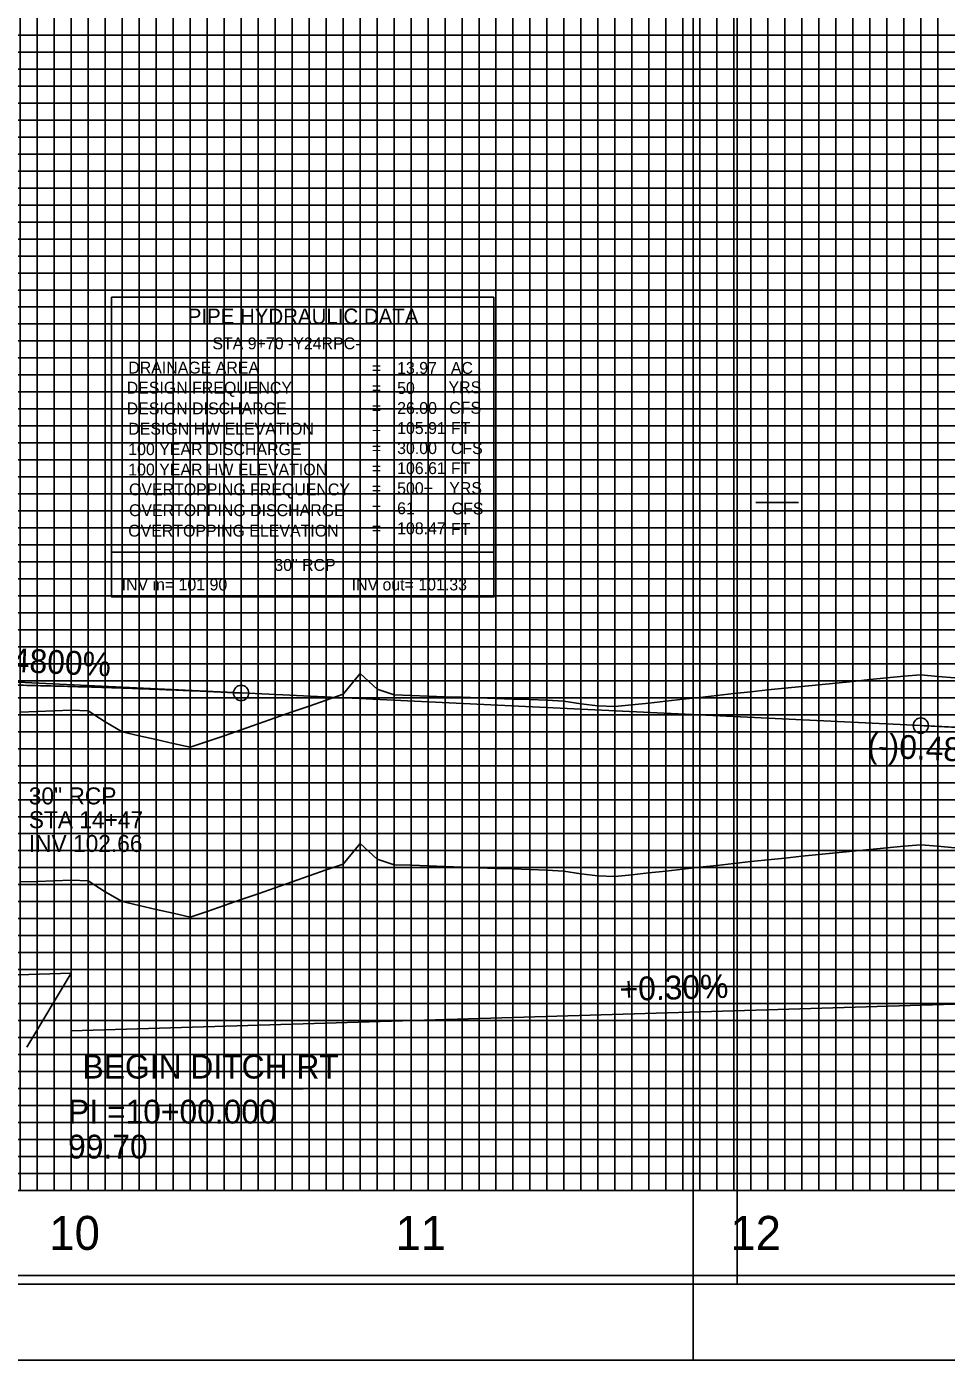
# Model space of a CAD drawing. Extents: x 2345490 to 2436403, y 465165 to 573888.
# Drawn here: x 2411882.2 to 2412152.8, y 527722 to 528114.5 of the extents above; entities that cross this region are included whole.
import ezdxf

# ---------------------------------------------------------------- set-up
doc = ezdxf.new("R2010")
doc.units = 0
for name, color, linetype in [('Old_Level_1', 7, 'Continuous'), ('Old_Level_18', 7, 'Continuous'), ('Old_Level_2', 7, 'Continuous'), ('Old_Level_3', 7, 'Continuous'), ('Old_Level_4', 7, 'Continuous'), ('Old_Level_41', 7, 'Continuous'), ('Old_Level_42', 7, 'Continuous'), ('Old_Level_43', 7, 'Continuous'), ('Old_Level_50', 7, 'Continuous'), ('Old_Level_51', 7, 'Continuous'), ('Old_Level_52', 7, 'Continuous'), ('Old_Level_62', 7, 'Continuous'), ('Old_Level_63', 7, 'Continuous')]:
    doc.layers.add(name, color=color, linetype=linetype)

msp = doc.modelspace()

# ---------------------------------------------------------------- linework, layer by layer
at = {"layer": 'Old_Level_1'}
for points in [[(2411895.325, 527863.353), (2411900.325, 527863.1465), (2411905.325, 527859.92), (2411910.325, 527857.03625), (2411915.325, 527855.8775), (2411920.325, 527854.73775), (2411925.325, 527853.61675), (2411930.325, 527852.51475), (2411935.325, 527854.12925), (2411940.325, 527855.877), (2411945.325, 527857.6245), (2411950.325, 527859.371), (2411955.325, 527861.11725), (2411960.325, 527862.8625), (2411965.325, 527864.60725), (2411970.325, 527866.35125), (2411975.325, 527868.0945), (2411980.325, 527874.1555), (2411985.325, 527869.5275), (2411990.325, 527867.9145), (2411995.325, 527867.72675), (2412000.325, 527867.54175), (2412005.325, 527867.36025), (2412010.325, 527867.18175), (2412015.325, 527867.0065), (2412020.325, 527866.8345), (2412025.325, 527866.66575), (2412030.325, 527866.5), (2412035.325, 527866.3375), (2412040.325, 527865.99575), (2412045.325, 527865.25), (2412050.325, 527864.65625), (2412055.325, 527864.43675), (2412060.325, 527864.91075), (2412065.325, 527865.47175), (2412070.325, 527866.032), (2412075.325, 527866.5915), (2412080.325, 527867.15025), (2412085.325, 527867.70825), (2412090.325, 527868.2655), (2412095.325, 527868.82225), (2412100.325, 527869.36725), (2412105.325, 527869.87), (2412110.325, 527870.372), (2412115.325, 527870.87325), (2412120.325, 527871.3735), (2412125.325, 527871.873), (2412130.325, 527872.37175), (2412135.325, 527872.8695), (2412140.325, 527873.36675), (2412145.325, 527873.74225), (2412150.325, 527873.32075), (2412155.325, 527872.89975)], [(2411880.325, 527862.82425), (2411885.325, 527862.99775), (2411890.325, 527863.174), (2411895.325, 527863.353)]]:
    msp.add_lwpolyline(points, dxfattribs=at)
at = {"layer": 'Old_Level_18'}
msp.add_lwpolyline([(2412345.325, 528797.04275), (2410845.325, 528797.04275), (2410845.325, 527747.04275), (2412345.325, 527747.04275)], close=True, dxfattribs=at)
at = {"layer": 'Old_Level_2'}
for p, q in [((2411945.325, 527918.443), (2411848.072, 527923.11125)), ((2411945.325, 527918.443), (2412145.325, 527908.843)), ((2412145.325, 527908.843), (2412242.57825, 527904.175))]:
    msp.add_line(p, q, dxfattribs=at)
for centre in [(2411945.325, 527918.443), (2412145.325, 527908.843)]:
    msp.add_circle(centre, 2.25, dxfattribs=at)
for points in [[(2411745.325, 527920.243), (2411749.325, 527920.36), (2411753.325, 527920.47075), (2411757.325, 527920.575), (2411761.325, 527920.67325), (2411765.325, 527920.765), (2411769.325, 527920.85075), (2411773.325, 527920.93025), (2411777.325, 527921.0035), (2411781.325, 527921.0705), (2411785.325, 527921.131), (2411789.325, 527921.1855), (2411793.325, 527921.23375), (2411797.325, 527921.27575), (2411801.325, 527921.3115), (2411805.325, 527921.341), (2411809.325, 527921.3645), (2411813.325, 527921.3815), (2411817.325, 527921.39225), (2411821.325, 527921.39675), (2411825.325, 527921.395), (2411829.325, 527921.38725), (2411833.325, 527921.373), (2411837.325, 527921.35275), (2411841.325, 527921.326), (2411845.325, 527921.293), (2411849.325, 527921.254), (2411853.325, 527921.20875), (2411857.325, 527921.157), (2411861.325, 527921.09925), (2411865.325, 527921.035), (2411869.325, 527920.96475), (2411873.325, 527920.88825), (2411877.325, 527920.8055), (2411881.325, 527920.7165), (2411885.325, 527920.621), (2411889.325, 527920.5195), (2411893.325, 527920.41175), (2411897.325, 527920.29775), (2411901.325, 527920.1775), (2411905.325, 527920.051), (2411909.325, 527919.9185), (2411913.325, 527919.7795), (2411917.325, 527919.63425), (2411921.325, 527919.48275), (2411925.325, 527919.325), (2411929.325, 527919.16125), (2411933.325, 527918.991), (2411937.325, 527918.81475), (2411941.325, 527918.632), (2411945.325, 527918.443)], [(2412145.325, 527908.843), (2412149.325, 527908.6555), (2412153.325, 527908.47675), (2412157.325, 527908.3065), (2412161.325, 527908.14525), (2412165.325, 527907.99275), (2412169.325, 527907.849), (2412173.325, 527907.714), (2412177.325, 527907.58775), (2412181.325, 527907.4705), (2412185.325, 527907.36175), (2412189.325, 527907.262), (2412193.325, 527907.17075), (2412197.325, 527907.0885), (2412201.325, 527907.015), (2412205.325, 527906.95), (2412209.325, 527906.894), (2412213.325, 527906.84675), (2412217.325, 527906.8085), (2412221.325, 527906.77875), (2412225.325, 527906.75775), (2412229.325, 527906.74575), (2412233.325, 527906.74225), (2412237.325, 527906.74775), (2412241.325, 527906.76175), (2412245.325, 527906.78475), (2412249.325, 527906.8165), (2412253.325, 527906.857), (2412257.325, 527906.90625), (2412261.325, 527906.96425), (2412265.325, 527907.031), (2412269.325, 527907.10675), (2412273.325, 527907.191), (2412277.325, 527907.28425), (2412281.325, 527907.386), (2412285.325, 527907.49675), (2412289.325, 527907.61625), (2412293.325, 527907.7445), (2412297.325, 527907.8815), (2412301.325, 527908.02725), (2412305.325, 527908.18175), (2412309.325, 527908.345), (2412313.325, 527908.51725), (2412317.325, 527908.698), (2412321.325, 527908.88775), (2412325.325, 527909.086), (2412329.325, 527909.29325), (2412333.325, 527909.50925), (2412337.325, 527909.734), (2412341.325, 527909.9675), (2412345.325, 527910.20975)]]:
    msp.add_spline(points, degree=3, dxfattribs=at)
at = {"layer": 'Old_Level_3'}
for p, q in [((2411407.325, 527821.24275), (2411895.325, 527835.94275)), ((2411882.24895, 527814.21295), (2411895.325, 527835.94275)), ((2411895.325, 527819.04275), (2412270.325, 527830.34275)), ((2411895.33153, 527801.91856), (2411895.325, 527819.04275)), ((2411895.33153, 527801.91856), (2411895.32517, 527819.543)), ((2411895.33153, 527801.91856), (2411895.32517, 527819.543)), ((2411895.33153, 527801.91856), (2411963.55128, 527801.91856))]:
    msp.add_line(p, q, dxfattribs=at)
at = {"layer": 'Old_Level_4'}
for p, q in [((2411907.22562, 528034.91149), (2412019.72562, 528034.91149)), ((2411907.22562, 527959.91149), (2411907.22562, 528034.91149)), ((2412019.72562, 528034.91149), (2412019.72562, 527959.91149)), ((2412019.72562, 527959.91149), (2411907.22562, 527959.91149))]:
    msp.add_line(p, q, dxfattribs=at)
msp.add_lwpolyline([(2411907.22562, 527959.91149), (2412019.72562, 527959.91149), (2412019.72562, 527946.69649), (2411907.22562, 527946.69649)], close=True, dxfattribs=at)
at = {"layer": 'Old_Level_41'}
for p, q in [((2412096.825, 527974.54275), (2412109.325, 527974.54275)), ((2412345.325, 527772.04275), (2410845.325, 527772.04275))]:
    msp.add_line(p, q, dxfattribs=at)
for points in [[(2411870.325, 528797.04275), (2411870.325, 527772.04275), (2411920.325, 527772.04275), (2411920.325, 528797.04275)], [(2411895.325, 528797.04275), (2411895.325, 527772.04275), (2411945.325, 527772.04275), (2411945.325, 528797.04275)], [(2411970.325, 528797.04275), (2411970.325, 527772.04275), (2412020.325, 527772.04275), (2412020.325, 528797.04275)], [(2411995.325, 528797.04275), (2411995.325, 527772.04275), (2412045.325, 527772.04275), (2412045.325, 528797.04275)], [(2412070.325, 528797.04275), (2412070.325, 527772.04275), (2412120.325, 527772.04275), (2412120.325, 528797.04275)], [(2412095.325, 528797.04275), (2412095.325, 527772.04275), (2412145.325, 527772.04275), (2412145.325, 528797.04275)], [(2412345.325, 528097.04275), (2410845.325, 528097.04275), (2410845.325, 528047.04275), (2412345.325, 528047.04275)], [(2412345.325, 528022.04275), (2410845.325, 528022.04275), (2410845.325, 528072.04275), (2412345.325, 528072.04275)], [(2412345.325, 527997.04275), (2410845.325, 527997.04275), (2410845.325, 527947.04275), (2412345.325, 527947.04275)], [(2412345.325, 527897.04275), (2410845.325, 527897.04275), (2410845.325, 527847.04275), (2412345.325, 527847.04275)], [(2412345.325, 527822.04275), (2410845.325, 527822.04275), (2410845.325, 527872.04275), (2412345.325, 527872.04275)], [(2412345.325, 527797.04275), (2410845.325, 527797.04275)]]:
    msp.add_lwpolyline(points, dxfattribs=at)
at = {"layer": 'Old_Level_42'}
msp.add_lwpolyline([(2412345.325, 527922.04275), (2410845.325, 527922.04275), (2410845.325, 527972.04275), (2412345.325, 527972.04275)], dxfattribs=at)
at = {"layer": 'Old_Level_43'}
for points in [[(2411880.325, 528797.04275), (2411880.325, 527772.04275), (2411885.325, 527772.04275), (2411885.325, 528797.04275)], [(2411890.325, 528797.04275), (2411890.325, 527772.04275), (2411900.325, 527772.04275), (2411900.325, 528797.04275)], [(2411905.325, 528797.04275), (2411905.325, 527772.04275), (2411910.325, 527772.04275), (2411910.325, 528797.04275)], [(2411915.325, 528797.04275), (2411915.325, 527772.04275)], [(2411915.325, 527772.04275), (2411925.325, 527772.04275), (2411925.325, 528797.04275)], [(2411930.325, 528797.04275), (2411930.325, 527772.04275), (2411935.325, 527772.04275), (2411935.325, 528797.04275)], [(2411940.325, 528797.04275), (2411940.325, 527772.04275), (2411950.325, 527772.04275), (2411950.325, 528797.04275)], [(2411955.325, 528797.04275), (2411955.325, 527772.04275), (2411960.325, 527772.04275), (2411960.325, 528797.04275)], [(2411965.325, 528797.04275), (2411965.325, 527772.04275), (2411975.325, 527772.04275), (2411975.325, 528797.04275)], [(2411980.325, 528797.04275), (2411980.325, 527772.04275), (2411985.325, 527772.04275), (2411985.325, 528797.04275)], [(2411990.325, 528797.04275), (2411990.325, 527772.04275), (2412000.325, 527772.04275), (2412000.325, 528797.04275)], [(2412005.325, 528797.04275), (2412005.325, 527772.04275), (2412010.325, 527772.04275), (2412010.325, 528797.04275)], [(2412015.325, 528797.04275), (2412015.325, 527772.04275), (2412025.325, 527772.04275), (2412025.325, 528797.04275)], [(2412030.325, 528797.04275), (2412030.325, 527772.04275), (2412035.325, 527772.04275), (2412035.325, 528797.04275)], [(2412040.325, 528797.04275), (2412040.325, 527772.04275), (2412050.325, 527772.04275), (2412050.325, 528797.04275)], [(2412055.325, 528797.04275), (2412055.325, 527772.04275), (2412060.325, 527772.04275), (2412060.325, 528797.04275)], [(2412065.325, 528797.04275), (2412065.325, 527772.04275), (2412075.325, 527772.04275), (2412075.325, 528797.04275)], [(2412080.325, 528797.04275), (2412080.325, 527772.04275), (2412085.325, 527772.04275), (2412085.325, 528797.04275)], [(2412090.325, 528797.04275), (2412090.325, 527772.04275), (2412100.325, 527772.04275), (2412100.325, 528797.04275)], [(2412105.325, 528797.04275), (2412105.325, 527772.04275), (2412110.325, 527772.04275), (2412110.325, 528797.04275)], [(2412115.325, 528797.04275), (2412115.325, 527772.04275), (2412125.325, 527772.04275), (2412125.325, 528797.04275)], [(2412130.325, 528797.04275), (2412130.325, 527772.04275), (2412135.325, 527772.04275), (2412135.325, 528797.04275)], [(2412140.325, 528797.04275), (2412140.325, 527772.04275), (2412150.325, 527772.04275), (2412150.325, 528659.49275)], [(2412295.325, 528112.04275), (2410895.325, 528112.04275), (2410895.325, 528107.04275), (2412295.325, 528107.04275)], [(2412295.325, 528102.04275), (2410895.325, 528102.04275), (2410895.325, 528092.04275), (2412295.325, 528092.04275)], [(2412295.325, 528087.04275), (2410895.325, 528087.04275), (2410895.325, 528082.04275), (2412295.325, 528082.04275)], [(2412295.325, 528077.04275), (2410895.325, 528077.04275), (2410895.325, 528067.04275), (2412295.325, 528067.04275)], [(2412295.325, 528062.04275), (2410895.325, 528062.04275), (2410895.325, 528057.04275), (2412295.325, 528057.04275)], [(2412295.325, 528052.04275), (2410895.325, 528052.04275), (2410895.325, 528042.04275), (2412295.325, 528042.04275)], [(2412295.325, 528037.04275), (2410895.325, 528037.04275), (2410895.325, 528032.04275), (2412295.325, 528032.04275)], [(2412295.325, 528027.04275), (2410895.325, 528027.04275), (2410895.325, 528017.04275), (2412295.325, 528017.04275)], [(2412295.325, 528012.04275), (2410895.325, 528012.04275), (2410895.325, 528007.04275), (2412295.325, 528007.04275)], [(2412295.325, 528002.04275), (2410895.325, 528002.04275), (2410895.325, 527992.04275), (2412295.325, 527992.04275)], [(2412295.325, 527987.04275), (2410895.325, 527987.04275), (2410895.325, 527982.04275), (2412295.325, 527982.04275)], [(2412295.325, 527977.04275), (2410895.325, 527977.04275)], [(2410895.325, 527967.04275), (2412295.325, 527967.04275)], [(2412295.325, 527962.04275), (2410895.325, 527962.04275), (2410895.325, 527957.04275), (2412295.325, 527957.04275)], [(2412295.325, 527952.04275), (2410895.325, 527952.04275)], [(2410895.325, 527942.04275), (2412295.325, 527942.04275)], [(2412295.325, 527937.04275), (2410895.325, 527937.04275), (2410895.325, 527932.04275), (2412295.325, 527932.04275)], [(2412295.325, 527927.04275), (2410895.325, 527927.04275), (2410895.325, 527917.04275), (2412295.325, 527917.04275)], [(2412295.325, 527912.04275), (2410895.325, 527912.04275), (2410895.325, 527907.04275), (2412295.325, 527907.04275)], [(2412295.325, 527902.04275), (2410895.325, 527902.04275), (2410895.325, 527892.04275), (2412295.325, 527892.04275)], [(2412295.325, 527887.04275), (2410895.325, 527887.04275), (2410895.325, 527882.04275), (2412295.325, 527882.04275)], [(2412295.325, 527877.04275), (2410895.325, 527877.04275), (2410895.325, 527867.04275), (2412295.325, 527867.04275)], [(2412295.325, 527862.04275), (2410895.325, 527862.04275), (2410895.325, 527857.04275), (2412295.325, 527857.04275)], [(2412295.325, 527852.04275), (2410895.325, 527852.04275), (2410895.325, 527842.04275), (2412295.325, 527842.04275)], [(2412295.325, 527837.04275), (2410895.325, 527837.04275), (2410895.325, 527832.04275), (2412295.325, 527832.04275)], [(2412295.325, 527827.04275), (2410895.325, 527827.04275), (2410895.325, 527817.04275), (2412295.325, 527817.04275)], [(2412295.325, 527812.04275), (2410895.325, 527812.04275), (2410895.325, 527807.04275), (2412295.325, 527807.04275)], [(2412295.325, 527802.04275), (2410895.325, 527802.04275), (2410895.325, 527792.04275), (2412295.325, 527792.04275)], [(2412295.325, 527787.04275), (2410895.325, 527787.04275), (2410895.325, 527782.04275), (2412295.325, 527782.04275)], [(2412295.325, 527777.04275), (2410895.325, 527777.04275)]]:
    msp.add_lwpolyline(points, dxfattribs=at)
at = {"layer": 'Old_Level_50'}
msp.add_line((2412078.325, 527722.04275), (2412078.325, 527722.04275), dxfattribs=at)
for points in [[(2412357.825, 528799.59275), (2410691.325, 528799.59275), (2410691.325, 527744.49275), (2412357.825, 527744.49275)], [(2413757.825, 528799.59275), (2412091.325, 528799.59275), (2412091.325, 527744.49275), (2413757.825, 527744.49275)]]:
    msp.add_lwpolyline(points, close=True, dxfattribs=at)
at = {"layer": 'Old_Level_51'}
for points in [[(2412362.325, 528822.04275), (2410678.325, 528822.04275), (2410678.325, 527722.04275), (2412362.325, 527722.04275)], [(2413762.325, 528822.04275), (2412078.325, 528822.04275), (2412078.325, 527722.04275), (2413762.325, 527722.04275)]]:
    msp.add_lwpolyline(points, close=True, dxfattribs=at)
at = {"layer": 'Old_Level_52'}
msp.add_line((2412091.325, 527744.49275), (2412091.325, 527744.49275), dxfattribs=at)
at = {"layer": 'Old_Level_63'}
msp.add_line((2410895.325, 527772.04275), (2413081.64925, 527772.04275), dxfattribs=at)
for points in [[(2411895.325, 527913.353), (2411900.325, 527913.1465), (2411905.325, 527909.92), (2411910.325, 527907.03625), (2411915.325, 527905.8775), (2411920.325, 527904.73775), (2411925.325, 527903.61675), (2411930.325, 527902.51475), (2411935.325, 527904.12925), (2411940.325, 527905.877), (2411945.325, 527907.6245), (2411950.325, 527909.371), (2411955.325, 527911.11725), (2411960.325, 527912.8625), (2411965.325, 527914.60725), (2411970.325, 527916.35125), (2411975.325, 527918.0945), (2411980.325, 527924.1555), (2411985.325, 527919.5275), (2411990.325, 527917.9145), (2411995.325, 527917.72675), (2412000.325, 527917.54175), (2412005.325, 527917.36025), (2412010.325, 527917.18175), (2412015.325, 527917.0065), (2412020.325, 527916.8345), (2412025.325, 527916.66575), (2412030.325, 527916.5), (2412035.325, 527916.3375), (2412040.325, 527915.99575), (2412045.325, 527915.25), (2412050.325, 527914.65625), (2412055.325, 527914.43675), (2412060.325, 527914.91075), (2412065.325, 527915.47175), (2412070.325, 527916.032), (2412075.325, 527916.5915), (2412080.325, 527917.15025), (2412085.325, 527917.70825), (2412090.325, 527918.2655), (2412095.325, 527918.82225), (2412100.325, 527919.36725), (2412105.325, 527919.87), (2412110.325, 527920.372), (2412115.325, 527920.87325), (2412120.325, 527921.3735), (2412125.325, 527921.873), (2412130.325, 527922.37175), (2412135.325, 527922.8695), (2412140.325, 527923.36675), (2412145.325, 527923.74225), (2412150.325, 527923.32075), (2412155.325, 527922.89975)], [(2411880.325, 527912.82425), (2411885.325, 527912.99775), (2411890.325, 527913.174), (2411895.325, 527913.353)]]:
    msp.add_lwpolyline(points, dxfattribs=at)

# ---------------------------------------------------------------- texts
at = {"layer": 'Old_Level_2'}
for p in [(2411860.5975, 527925.5135), (2412129.48175, 527899.61472)]:
    msp.add_text('(-)0.4800%', height=7.000001, rotation=357.2519111, dxfattribs=at).set_placement(p)
at = {"layer": 'Old_Level_3'}
for s, height, rotation, p in [('30" RCP', 4.999999, 0.0000389, (2411882.86074, 527885.6573)), ('STA 14+47', 4.999999, 0.0000389, (2411882.86074, 527878.6573)), ('INV 102.66', 4.999999, 0.0000389, (2411882.86074, 527871.6573)), ('+0.30%', 7.000001, 1.7253956, (2412056.78598, 527827.77329)), ('BEGIN DITCH RT', 7.0000005, 360, (2411898.67324, 527804.97066)), ('PI =10+00.000', 7.0000005, 360, (2411894.41156, 527791.73319)), ('99.70', 7.000001, 360, (2411894.41387, 527781.43548))]:
    msp.add_text(s, height=height, rotation=rotation, dxfattribs=at).set_placement(p)
at = {"layer": 'Old_Level_4'}
for s, height, p in [('PIPE HYDRAULIC DATA', 4.49985, (2411929.62562, 528027.08649)), ('STA 9+70 -Y24RPC-', 3.4998, (2411936.87912, 528019.58624)), ('DRAINAGE AREA', 3.49995, (2411912.12562, 528012.46149)), ('=        ', 3.49995, (2411983.77562, 528012.36149)), ('13.97', 3.49995, (2411991.23612, 528012.36104)), ('AC', 3.49995, (2412007.05062, 528012.36149)), ('DESIGN FREQUENCY', 3.49995, (2411911.67562, 528006.53649)), ('=        ', 3.49995, (2411983.77562, 528006.46149)), ('50', 3.49995, (2411991.23612, 528006.46109)), ('YRS', 3.49995, (2412006.35062, 528006.66149)), ('DESIGN DISCHARGE', 3.49995, (2411911.67562, 528000.46149)), ('=        ', 3.49995, (2411983.77562, 528000.56149)), ('26.00', 3.49995, (2411991.23612, 528000.56114)), ('CFS', 3.49995, (2412006.57562, 528000.63649)), ('DESIGN HW ELEVATION', 3.49995, (2411912.12562, 527994.46149)), ('=        ', 3.49995, (2411983.77562, 527994.66149)), ('105.91', 3.49995, (2411991.23612, 527994.66119)), ('FT', 3.49995, (2412007.05062, 527994.66149)), ('100 YEAR DISCHARGE', 3.49995, (2411912.12562, 527988.46149)), ('=        ', 3.49995, (2411983.77562, 527988.76149)), ('30.00', 3.49995, (2411991.23612, 527988.76124)), ('CFS', 3.49995, (2412007.05062, 527988.76149)), ('100 YEAR HW ELEVATION', 3.49995, (2411912.12562, 527982.46149)), ('=        ', 3.49995, (2411983.77562, 527982.86149)), ('106.61', 3.49995, (2411991.23612, 527982.86129)), ('FT', 3.49995, (2412007.05062, 527982.86149)), ('OVERTOPPING FREQUENCY', 3.49995, (2411912.35062, 527976.61149)), ('=        ', 3.49995, (2411983.77562, 527976.96149)), ('500+', 3.49995, (2411991.23612, 527976.96134)), ('YRS', 3.49995, (2412006.57562, 527977.01149)), ('OVERTOPPING DISCHARGE', 3.49995, (2411912.35062, 527970.48649)), ('=        ', 3.49995, (2411983.77562, 527971.06149)), ('61', 3.49995, (2411991.23612, 527971.06139)), ('CFS', 3.49995, (2412007.27562, 527970.98649)), ('OVERTOPPING ELEVATION', 3.49995, (2411912.12562, 527964.46149)), ('=        ', 3.49995, (2411983.77562, 527965.16149)), ('108.47', 3.49995, (2411991.23612, 527965.16144)), ('FT', 3.49995, (2412007.05062, 527964.96149)), ('30" RCP', 3.4998, (2411955.10962, 527954.37074)), ('INV in= 101.90', 3.4998, (2411910.15812, 527948.62349)), ('INV out= 101.33', 3.4998, (2411977.83487, 527948.62349))]:
    msp.add_text(s, height=height, dxfattribs=at).set_placement(p)
at = {"layer": 'Old_Level_62'}
for s, p in [('10', (2411888.9085, 527754.543)), ('11', (2411990.748, 527754.543)), ('12', (2412089.29625, 527754.543))]:
    msp.add_text(s, height=10.000001, dxfattribs=at).set_placement(p)

doc.saveas('drawing.dxf')
